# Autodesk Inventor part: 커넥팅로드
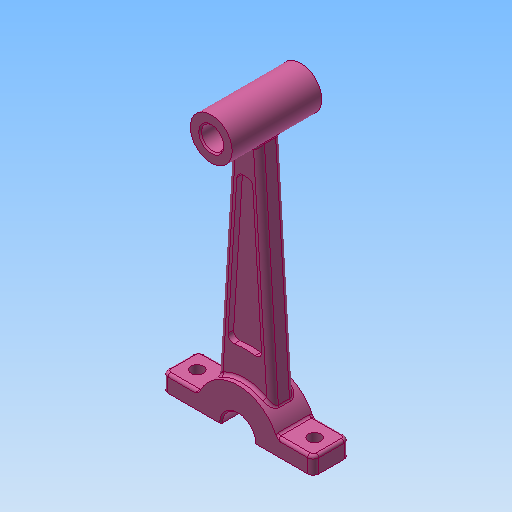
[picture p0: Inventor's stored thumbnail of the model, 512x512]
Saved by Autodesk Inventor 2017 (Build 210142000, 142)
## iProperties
Created: 2016-11
Part Number: 커넥팅로드
Material: 알루미늄 6061
Document SubType Name: Modeling
Designer: mduedu
Density: 2.71 g/cm^3
Mass: 44.5487 g
Surface Area: 86.7069 cm^2
Volume: 16.4386 cm^3
Appearance: 분홍색
Author: mduedu
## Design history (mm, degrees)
sketch "스케치1" dims "d0" = 30, "d3" = 15
  geometry: L1 (0, 0)-(0, 96); L2 (-5, 90.41)-(-10, 11.18); L3 (5, 90.41)-(10, 11.18); C1 r 6 at (0, 0); C2 r 4 at (0, 96); 3 further points
  constraints: 6 end point, 4 coincident, 2 centre point, 2 symmetric about line, 1 vertical, 6 other
  dimensions: "d1" = 12 diameter of C1; "d2" = 8 diameter of C2; "d4" = 96 distance of L1.start L1.end; "d6" = 10 distance from line of L1 L2.end; "d7" = 5 distance from line of L1 L2.start
extrude "돌출1" new body sketch "스케치1" stored distance "d8" = 13; taper "d9" = 0 deg
extrude "돌출2" join sketch "스케치1" stored distance "d10" = 32; taper "d11" = 0 deg
sketch "스케치2"
  geometry: L1 (5, 90.41)-(10, 11.18) reference; L2 (-5, 90.41)-(-10, 11.18) reference; A1 r 7.5 centre (0, 96) between (5, 90.41) and (-5, 90.41) reference; A2 r 15 centre (0, 0) between (10, 11.18) and (-10, 11.18) reference
extrude "돌출3" join sketch "스케치2" stored distance "d12" = 8; taper "d13" = 0 deg
sketch "스케치3"
  geometry: L1 (-2.732, 78.715)-(-6.171, 24.226); L2 (2.732, 78.715)-(6.171, 24.226); L3 (0, 78.5)-(0, 25); A1 r 17.5 centre (0, 96) between (-2.732, 78.715) and (2.732, 78.715); A2 r 25 centre (0, 0) between (6.171, 24.226) and (-6.171, 24.226); 9 further points; 2 other entities
  constraints: 6 end point, 6 point on circle, 2 centre point, 1 symmetric about line, 1 vertical alignment, 6 other
  dimensions: "d18" = 10 dimension on A1; "d19" = 10 dimension on A2; "d20" = 3 dimension on L1
extrude "돌출4" cut sketch "스케치3" distance "d21" = 2; taper "d22" = 0 deg
fillet "모깎기1" dims "d23" = 2
fillet "모깎기2" dims "d24" = 2
fillet "모깎기3" dims "d25" = 1
chamfer "모따기1" distance "d26" = 0.5; stored, may be unused: second distance "d27" = 2, angle "d28" = 45 deg
sketch "스케치4"
  geometry: L1 (-27, -6)-(-13.748, -6); L2 (27, -6)-(27, 6); L3 (27, 6)-(13.748, 6); L4 (-27, 6)-(-27, -6); L5 (-27, -6)-(27, 6); L6 (27, -6)-(-27, 6); L7 (-13.748, 6)-(-27, 6); L8 (13.748, 6)-(-13.748, 6); L9 (13.748, -6)-(27, -6); L10 (-13.748, -6)-(13.748, -6); A1 r 15 centre (0, 0) between (-13.748, 6) and (13.748, 6) reference; 1 further point
  constraints: 20 end point, 10 parallel, 4 point on circle, 3 horizontal, 3 perpendicular, 2 midpoint
  dimensions: "d29" = 54 distance of L1.start L2.start; "d31" = 12 distance of L2.start L2.end
extrude "돌출5" join sketch "스케치4" stored distance "d32" = 0; taper "d33" = 0 deg
fillet "모깎기4" dims "d34" = 2
fillet "모깎기5" dims "d35" = 1
fillet "모깎기6" dims "d36" = 1
sketch "스케치5"
  geometry: L1 (1, 0)-(1, 9) reference; L2 (-18.5, 20.5)-(-33.5, 20.5) reference; L3 (-33.5, -11.5)-(-18.5, -11.5) reference; L4 (-26, 20.5)-(-26, -11.5); 3 further points
  constraints: 2 end point, 2 midpoint, 1 horizontal alignment, 1 symmetric about line
  dimensions: "d37" = 6 distance from line of point (-5, 4.5) L1
feature "분할1"
sketch "스케치7"
  geometry: 2 further points
  constraints: 2 other
hole "구멍2" sketch "스케치7" at (-47, 4.5), (-5, 4.5) diameter "d45" = 4.5; stored, may be unused: countersink angle "d49" = 90 deg, drill point angle "d51" = 0 deg; dims "d46" = 6, "d47" = 4, "d48" = 2, "d50" = 8
node "솔리드1"
mirror "대칭1"
other parameters: "d16" = 4, "d17" = 4
